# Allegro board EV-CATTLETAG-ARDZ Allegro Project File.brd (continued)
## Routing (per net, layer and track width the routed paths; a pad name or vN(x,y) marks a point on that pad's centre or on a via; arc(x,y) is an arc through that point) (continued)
UNNAMED_4_CN6P_I91_N5: length 5.8
  BOTTOM w0.203: P1.5 3.81,21.59 R75.1
UNNAMED_4_CN6P_I91_N6: length 6.3
  BOTTOM w0.203: R76.1 5.11,20.35 P1.6
UNNAMED_4_CN8PA_I85_N4: length 7.4
  BOTTOM w0.635: R83.1 R82.1 ; R82.1 2.54,45.72 P2.4 ; R82.1 R81.1
UNNAMED_4_CN8PA_I85_N8: length 7.4
  BOTTOM w0.635: R85.1 2.57,35.59 P2.8 ; R85.1 R84.1 ; R85.1 R86.1
UNNAMED_4_CN8PA_I86_N1: length 2.1
  TOP w0.203: P5.1 50.75,17.73 R98.2
UNNAMED_4_CN8PA_I86_N2: length 2.4
  TOP w0.203: P5.2 49.67,20.32 49.63,20.27 49.59,20.27 49.56,20.24 49.21,20.24 48.68,19.71 R97.2
UNNAMED_4_CN8PA_I86_N3: length 2.4
  TOP w0.203: P5.3 50.25,22.3 R96.2
UNNAMED_4_CN8PA_I86_N4: length 2.7
  TOP w0.203: R95.2 49.48,24.08 P5.4
UNNAMED_4_CN8PA_I86_N5: length 3.7
  TOP w0.203: P5.5 49.21,26.34 49.2,26.34 48.68,25.82 R94.2
UNNAMED_4_CN8PA_I86_N6: length 2.1
  TOP w0.203: R93.2 50.8,30.48 P5.6
UNNAMED_4_CN8PA_I86_N7: length 2.1
  TOP w0.203: R92.2 50.75,32.97 P5.7
UNNAMED_4_CN8PA_I86_N8: length 2.1
  TOP w0.203: P5.8 50.75,35.51 R91.2
UNNAMED_4_CN10P_I82_N1: length 2.1
  TOP w0.203: R90.2 50.75,39.57 P4.1
UNNAMED_4_CN10P_I82_N2: length 2.1
  TOP w0.203: P4.2 50.75,42.11 R89.2
UNNAMED_4_CN10P_I82_N3: length 2.2
  TOP w0.203: R100.2 50.8,44.7 P4.3
UNNAMED_4_CN10P_I82_N9: length 2.1
  TOP w0.203: P4.9 50.75,59.89 R88.2
UNNAMED_4_CN10P_I82_N10: length 2.1
  TOP w0.203: R87.2 50.75,62.43 P4.10
UNNAMED_4_DIOLED_I16_N: length 8.5
  TOP w0.508: DS4.C 48.77,71.52 47.62,70.38 46.13,70.38 v1(45.31,69.57) 45.32,69.56 R43.1 45.32,68.5 Q4.1
  BOTTOM w0.203: v1(45.31,69.57) 45.33,69.55 R35.2
UNNAMED_4_DIOLED_I16_P: length 6
  TOP w0.508: DS4.A 50.97,70.8 50.75,70.58 48.89,70.58 47.98,69.67 47.19,69.67 46.91,69.38 R33.2
UNNAMED_4_DIOLED_I122_P: length 2.7
  TOP w0.381: DS2.A 48.46,11.25 v1(47.41,10.21)
  BOTTOM w0.381: R22.2 v1(47.41,10.21)
UNNAMED_4_DIOLED_I130_P: length 4.4
  TOP w0.381: DS3.A 47.29,7.42 v1(46.86,7.42)
  BOTTOM w0.381: R28.2 47.23,7.04 v1(46.86,7.42)
UNNAMED_4_DIOLED_I200_N: length 2.4
  TOP w0.381: R21.1 DS1.C
UNNAMED_4_FERRITE_I266_N2: length 1.4
  BOTTOM w0.381: R53.2 E2.2
UNNAMED_4_FERRITE_I267_N2: length 2
  BOTTOM w0.508: R66.2 25.04,5.94 E4.2
UNNAMED_4_FERRITE_I281_N1: length 2.5
  BOTTOM w0.381: R47.2 R48.2 E1.1
UNNAMED_4_FERRITE_I282_N1: length 2.5
  TOP w0.508: E3.1 19.18,13.29 R62.2 R61.2
UNNAMED_4_RES_I19_N1: length 1.5
  TOP w0.508: R31.2 32.33,66.79 R36.1
UNNAMED_4_RES_I44_N2: length 2.3
  TOP w0.508: R42.2 35.93,69.08 35.92,69.09 RT1.1
UNNAMED_4_RES_I45_N2: length 6.6
  TOP w0.508: R41.2 38.5,65.94 R44.2 40.14,66.61 R44.3
UNNAMED_4_RES_I100_N2: length 2.9
  TOP w0.508: R40.2 44.37,62.89 Q4.3
UNNAMED_4_RES_I121_N1: length 3.5
  BOTTOM w0.381: R20.1 48.84,11.08 Q1.1 ; R20.1 R19.2 ; R20.1 R1.2
UNNAMED_4_RES_I126_N1: length 2.7
  BOTTOM w0.381: Q1.3 48.22,7.36 R22.1
UNNAMED_4_RES_I129_N1: length 2
  BOTTOM w0.508: R28.1 44.98,6.69 Q2.3
UNNAMED_4_RES_I131_N2: length 3.6
  BOTTOM w0.381: R26.2 43.92,10.69 R27.1 ; R27.1 43.91,9.34 Q2.1 ; R27.1 R23.2
UNNAMED_4_RES_I245_N1: length 5
  BOTTOM w0.381: Q5.1 38.87,4.14 R50.2 R51.1 40.44,4.52 R49.2
UNNAMED_4_RES_I261_N2: length 4
  BOTTOM w0.508: Q6.1 20.09,9.1 R63.2 18.36,8.01 R65.1 R64.2
UNNAMED_4_RES_I271_N1: length 7
  BOTTOM w0.381: Q5.2 31.4,2.26 R53.1 31.11,2.56 R54.2
UNNAMED_4_RES_I272_N1: length 3.2
  BOTTOM w0.508: Q6.2 22.46,9.59 R67.2 25.03,9.59 R66.1

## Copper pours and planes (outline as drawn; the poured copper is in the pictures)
GND on TOP (solid shape): 28.47,80.65 28.47,72.44 28.42,72.39 26.76,72.39 26.74,72.42 26.74,73.91 25.16,73.91 25.16,80.47 25.47,80.77 28.34,80.77
GND on TOP (solid shape): 35.4,31.17 35.4,30.2 37.56,28.04 37.56,27.99 36.9,27.99 35.25,29.64 32.76,29.64 32.61,29.79 32.61,31.06 32.76,31.22 35.35,31.22
GND on TOP (solid shape): 43.5,52.88 43.5,51.87 42.61,50.98 37.92,50.98 37.92,52.5 42.49,52.5 43.07,53.09 43.3,53.09
GND on TOP (solid shape): 46.22,31.06 46.22,29.79 46.07,29.64 43.58,29.64 41.93,27.99 41.27,27.99 41.27,28.04 43.43,30.2 43.43,31.17 43.48,31.22 46.07,31.22
GND on TOP (solid shape): 40.79,19.3 41.34,18.75 41.34,15.09 41.06,14.81 40.1,14.81 39.62,15.29 39.62,16.64 37,19.25 36.44,19.25 36.44,20.8 38.65,20.8 39.29,21.44 40.79,21.44
GND on TOP (solid shape): 40.84,40.72 40.84,39.45 40.91,39.37 45.61,39.37 45.76,39.22 45.76,38.25 45.65,38.14 43.34,38.14 43.33,38.13 36.01,38.13 35.88,38.25 35.88,39.22 36.04,39.37 39.13,39.37 39.21,39.45 39.21,40.72 39.39,40.89 40.66,40.89
GND on BOTTOM (solid shape): 36.44,31.47 34.56,31.47 34.41,31.62 34.41,32.84 34.61,33.05 36.44,33.05
GND on BOTTOM (solid shape): 42.49,33.5 42.49,31.55 41.24,31.55 41.24,33.15 41.01,33.38 41.01,34.44 41.14,34.57 41.42,34.57
GND on BOTTOM (solid shape): 45.18,30.84 45.18,29.64 44.93,29.39 42,29.39 41.88,29.51 41.88,29.74 42.56,30.43 43.17,30.43 43.63,30.89 45.13,30.89
GND on TOP: outline of 250 points within 37.51,15.29 52.07,80.77
GND on TOP: 49.27,16.64 51.71,16.64 52.07,16.27 52.07,7.4 51.86,7.19 50.44,7.19 50.13,7.49 50.13,11.91 49.99,12.05 48.57,12.05 48.43,12.19 48.43,14.61 49.27,15.44
GND on TOP: outline of 195 points within 16.33,1.27 52.07,16.64
GND on TOP: 31.36,41.99 33.5,41.99 33.95,41.53 33.95,41 33.73,40.77 33.65,40.73 33.59,40.67 33.57,40.67 33.46,40.64 33.36,40.58 32.46,39.68 32.37,39.61 32.34,39.5 32.34,36.87 32.03,36.56 32.03,32.03 32.09,31.89 32.24,31.83 33.84,31.83 33.98,31.89 34.04,32.03 34.04,32.75 34.08,32.79 34.74,32.79 34.97,32.56 34.97,31.67 34.79,31.5 31.24,31.5 31.08,31.65 31.08,41.71
GND on TOP: 29.31,21.23 29.71,21.23 29.91,21.03 29.91,18.97 29.61,18.67 29.5,18.6 29.45,18.47 29.45,16.82 29.51,16.68 29.65,16.62 31.31,16.62 31.45,16.68 31.51,16.82 31.51,17.47 31.72,17.68 32.36,17.68 32.56,17.68 32.76,17.48 32.76,13.06 32.48,12.78 25.58,12.78 25.11,13.24 25.11,14.12 25.26,14.09 25.4,14.08 26.43,15.11 25.4,16.14 25.26,16.13 25.11,16.1 25.11,16.66 25.26,16.63 25.4,16.62 26.13,16.92 26.43,17.65 26.42,17.75 26.41,17.85 26.41,18.33 26.8,18.72 26.81,18.73
GND on TOP: outline of 237 points within 1.27,1.27 46.88,80.77
GND on BOTTOM: outline of 283 points within 1.27,1.27 48.02,60.12
GND on BOTTOM: 23.72,11.51 30.11,11.51 31.55,10.07 31.69,9.97 31.87,9.93 32.25,9.93 32.53,9.65 32.53,6.86 32.07,6.4 30.85,6.4 30.71,6.34 30.65,6.2 30.65,5.23 30.62,5.2 30.56,5.12 30.54,5.03 30.54,4.1 30.07,3.63 26.43,3.63 26.29,3.57 26.23,3.43 26.23,1.73 25.77,1.27 19.04,1.27 19.04,2.74 19.78,2.74 20.11,3.07 20.11,5.66 20.61,5.66 20.63,5.6 20.67,5.53 20.73,5.47 21.14,5.06 21.31,4.58 21.31,4.57 21.66,3.87 22.4,3.58 22.9,3.7 23.29,4.04 24.07,4.83 26.23,4.83 26.24,4.84 26.33,4.83 27.35,4.83 27.49,4.89 27.55,5.03 27.55,6.81 27.49,6.95 27.35,7.01 26.38,7.01 26.23,7.16 26.23,10.8 23.72,10.8
GND on BOTTOM: 43.78,24.64 39.46,24.64 40.86,23.24 44.34,23.24 44.8,23.7 44.8,24.1 44.7,24.21 44.21,24.21
GND on BOTTOM: outline of 173 points within 1.27,1.27 52.07,80.77
GND on BOTTOM: 45.36,39.37 45.59,39.37 45.74,39.22 45.74,34.14 45.78,33.91 45.91,33.72 46.17,33.46 46.17,29.39 45.97,29.18 45.66,29.18 45.4,29.45 45.4,32.82 45.36,32.94 45.26,33.01 45.23,33.02 44.85,33.4 44.85,33.5 44.82,33.68 44.72,33.83 44.49,34.05 44.49,34.08 44.44,34.22 44.37,34.35 44.37,35.59 45.08,36.3 45.15,36.37 45.18,36.47 45.18,39.19
GND on BOTTOM: outline of 170 points within 6.14,1.27 42.36,18.72
GND on L2_GND, L3_GND: 1.27,80.77 52.07,80.77 52.07,1.27 1.27,1.27
VDD_3V3 on TOP (solid shape): 44.37,50.22 44.37,49.89 44.95,49.3 44.95,49.17 44.93,49.15 43.12,49.15 43.12,49.35 44.01,50.24 44.34,50.24
VDD_3V3 on BOTTOM (solid shape): 24.71,43.2 24.71,40.81 24.61,40.71 24.08,40.71 23.21,41.58 22.68,41.58 22.47,41.78 22.47,42.85 22.68,43.05 23.65,43.05 23.88,43.28 24.63,43.28
B1OUT on TOP (solid shape): 34.31,27.48 34.31,27.15 33.83,26.67 33.83,24.56 33.06,24.56 33.06,26.67 32.68,27.05 32.68,27.41 32.78,27.51 34.28,27.51
B1OUT on TOP (solid shape): 36.09,27.74 38.07,27.74 38.12,27.69 38.12,27.56 37.76,27.2 35.76,27.2 35.4,26.85 32,26.85 31.74,27.1 31.74,28.17 32,28.42 35.4,28.42
B1OUT on BOTTOM (solid shape): 33.19,28.14 33.19,27.13 33.04,26.97 32.28,26.97 31.16,28.09 31.16,28.35 31.18,28.37 32.96,28.37
B2OUT on TOP (solid shape): 46.26,27.48 46.26,27.15 45.78,26.67 45.78,24.56 45.01,24.56 45.01,26.67 44.63,27.05 44.63,27.41 44.74,27.51 46.23,27.51
B2OUT on TOP (solid shape): 47.08,28.17 47.08,27.1 46.83,26.85 43.43,26.85 43.07,27.2 41.06,27.2 40.71,27.56 40.71,27.69 40.76,27.74 42.74,27.74 43.43,28.42 46.83,28.42
B2OUT on BOTTOM (solid shape): 47.14,28.83 47.14,27.53 46.58,26.97 45.76,26.97 45.59,27.15 45.59,28.09 46.45,28.96 47.01,28.96
B2OUT on BOTTOM (solid shape): 28.16,46.15 29.3,46.15 30.55,44.91 30.55,44.65 30.35,44.45 27.07,44.45 26.92,44.6 26.92,46.58 27.73,46.58
BMS_BAT on TOP (solid shape): 43.66,23.47 43.66,22.2 45.13,20.73 45.13,16.43 44.39,15.7 42.36,15.7 42.03,16.03 42.03,18.16 42.04,18.17 42.04,19.1 41.57,19.57 41.57,24.36 39.92,26.01 39.92,27.05 40.07,27.05
BMS_BAT on BOTTOM (solid shape): 45.08,20.93 45.08,20.47 44.47,19.86 44.47,17.3 44.29,17.12 43.27,17.12 41.12,19.28 41.12,20.27 41.29,20.45 41.8,20.45 42.41,21.06 44.95,21.06
BMS_BAT on BOTTOM (solid shape): 18.82,16.46 18.82,12.67 17.68,11.53 15.04,11.53 10.06,6.55 8.61,6.55 8.53,6.63 8.53,7.54 8.59,7.59 8.94,7.59 14.4,13.05 17.02,13.05 17.3,13.33 17.3,16.35 17.5,16.56 18.72,16.56
BMS_SYS on TOP (solid shape): 39.69,26.29 38.97,25.57 38.97,24.19 40.13,23.04 40.13,22.5 38.7,22.5 38.32,22.12 36.54,22.12 36.54,24.97 36.98,25.4 38.12,25.4 39.08,26.37 39.08,26.62 39.21,26.75 39.69,26.75
BMS_SYS on BOTTOM (solid shape): 38.35,24.49 38.35,23.98 38.22,23.85 35.27,23.85 35.15,23.98 35.15,24.13 36.21,25.2 37.64,25.2
L1OUT on TOP (solid shape): 43.4,34.37 43.31,34.19 43.27,33.99 43.28,33.9 43.3,33.81 42.97,33.48 42.26,33.48 41.83,33.91 41.83,37.44 41.85,37.47 43.4,37.47
L1OUT on BOTTOM (solid shape): 42.23,36.04 43.2,36.04 43.4,35.84 43.4,35.26 42.77,34.62 42.26,34.62 41.32,35.56 41.32,36.37 41.34,36.4 41.88,36.4
L1OUT on BOTTOM (solid shape): 29.89,31.57 29.89,30.53 29.66,30.3 28.25,30.3 27.76,29.82 26.95,29.82 26.82,29.95 26.82,31.54 27.05,31.78 29.69,31.78
L2OUT on TOP (solid shape): 40.81,33.91 40.38,33.48 39.67,33.48 39.27,33.88 39.34,34.04 39.36,34.21 39.33,34.41 39.24,34.59 39.24,37.44 39.26,37.47 40.81,37.47
L2OUT on BOTTOM (solid shape): 28.97,27.71 28.97,26.75 28.03,25.8 26.94,25.8 26.74,26.01 26.74,27.83 27.1,28.19 28.49,28.19
L2OUT on BOTTOM (solid shape): 28.19,42.34 29.33,42.34 29.33,41.86 28.92,41.45 28.92,41.07 28.49,40.64 27.02,40.64 27.02,43.03 27.5,43.03
L2OUT on BOTTOM (solid shape): 41.09,36.42 41.06,36.4 41.06,35.53 40.18,34.65 39.85,34.65 39.26,35.23 39.26,35.84 39.41,35.99 40.1,35.99 40.56,36.45 41.06,36.45
L3OUT on TOP (solid shape): 38.22,34.59 38.13,34.41 38.09,34.21 38.12,34.04 38.19,33.88 37.79,33.48 37.08,33.48 36.65,33.91 36.65,37.44 36.67,37.47 38.22,37.47
L3OUT on BOTTOM (solid shape): 38.19,35.84 38.19,35.1 37.74,34.65 36.92,34.65 36.09,35.48 36.09,35.84 36.24,35.99 38.04,35.99
SRC on TOP (solid shape): 42.29,58.52 43.46,58.52 43.66,58.31 43.66,57.2 42.67,56.21 42.67,53.89 42.52,53.75 37.15,53.75 36.26,54.64 36.26,54.81 37.3,54.81 37.84,55.35 40.09,55.35 40.64,55.9 40.64,56.34 40.63,56.34 40.63,58.04 39.93,58.74 39.2,58.74 38.33,59.61 38.33,59.81 38.68,60.17 40.64,60.17
UNNAMED_4_ADMAX20335_I34_B1LX on TOP (solid shape): 37.74,26.44 36.29,26.44 35.4,25.55 35.4,24.28 34.69,24.28 34.69,25.78 35.91,27 38.3,27
UNNAMED_4_ADMAX20335_I34_B2LX on TOP (solid shape): 44.14,25.78 44.14,24.28 43.43,24.28 43.43,25.55 42.54,26.44 41.09,26.44 40.53,27 42.92,27
UNNAMED_4_ADMAX20335_I34_L1OUT on TOP (solid shape): 42.97,32.46 40.4,29.9 40.33,29.9 40.33,30.45 42.26,32.39 42.26,33.07 42.97,33.07
UNNAMED_4_ADMAX20335_I34_L2OUT on TOP (solid shape): 40.38,30.94 40,30.56 39.67,30.89 39.67,33.07 40.38,33.07
UNNAMED_4_ADMAX20335_I34_L3OUT on TOP (solid shape): 37.79,32.36 39.69,30.45 39.69,29.87 39.67,29.84 39.64,29.84 37.08,32.41 37.08,33.07 37.79,33.07
UNNAMED_4_ADMAX20361_I6_LX on TOP (solid shape): 39.57,57.78 39.57,56.26 38.3,56.26 37.16,55.11 36.27,55.11 36.27,55.29 36.53,55.55 36.88,55.55 39.14,57.81 39.55,57.81
UNNAMED_4_CN2P_I136_N2 on BOTTOM (solid shape): 10.66,4.68 10.66,3.43 9.62,2.39 3.7,2.39 3.19,2.9 3.19,3.96 4.16,4.93 10.41,4.93
UNNAMED_4_NCTESTPAD_I165_N1 on BOTTOM (solid shape): 16,20.5 16,13.84 15.79,13.64 13.91,13.64 12.16,15.39 12.16,22.53 13.96,22.53

Small or netless copper shapes (teardrops, artwork), in the pictures only: 66 on BOTTOM, 68 on TOP, 2 on L2_GND, 2 on L3_GND

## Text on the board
Ref Des/Silkscreen Bottom: K | GND | P7 | TMP | SECONDARY SIDE | EV-CATTLETAG-ARDZ | 08-079920 REV B Z | P6 | SRC | LOAD | 5 | 6 | BAT
User.Comments: COMPONENT KEEPOUT AREA | COMPONENTS GREATER THAN 1.5MM | -R77,R79 | -R29 | -R50,R64 | -R51,R65 | -R54,R67 | -C23,C26 | -P3 | -R9,R11,R16,R18,R42,R47,R61,R71,R73,R82,R83,R84,R85,R97 | -R24,R25,R30,R56,R57,R58,R59,R60 | 6.    THE FOLLOWING PARTS ARE DNI(DO NOT INSTALL): | A. P1 | B. P2 | C. P4 | D. P5 | 5.    DO NOT TRIM EXCESS PINS FOR THE FOLLOWING LOCATIONS | WITH LEAD-FREE AND RoHS PCB ASSEMBLY STANDARDS (EU RoHS | DIRECTIVE 2002/95/EC). | 4.    RoHS COMPLIANCE. ASSEMBLY VENDOR SHOULD ASSURE COMPLIANCE
Ref Des/Assembly Top: WIRE ENTRY
Ref Des/Silkscreen Top: 5 | 6 | LOAD | 1 | 2 | 8 | BAT | GND | 10
PAGE_OUTLINE: B | B1 | ECR-116886 | ECR-119049(UPDATE DNI LIST ON ASSY NOTES ONLY) | (NO CHANGE ON LAYOUT AND FAB FILES) | 05DEC23 | 26JAN24 | E. REYTA | EV-CATTLETAG-ARDZ
DIMENSION: -0.60IN | "0" | 2.63IN | DIA MAX | TENTED VIA | SEE FAB NOTES NO. 20 | -0.30IN | 1.80IN
User.10: L2 Internal GND | 08-      -07
User.11: L3 Internal GND | 08-      -08
User.12: FAB NOTES REVISION: 2ND NOVEMBER 2022 | 8.   IMPEDANCE REQUIREMENTS: IF NO STACKUP IS DEFINED, THE VENDOR IS ALLOWED TO ADJUST THE DIELECTRIC | 13.  PLATING SPECIFICATION: | 9.   FILLET OPTIONS TO ENHANCE RELIABILITY AT PAD JUNCTIONS WHERE SPACING PERMITS. | 10.  THIEVING: | 11.  LAYER TO LAYER REGISTRATION SHALL BE WITHIN 0.003 INCHES. | 12.  DRILL SIZES ARE FINISHED HOLE SIZES. ALL HOLES SHALL BE LOCATED WITHIN 0.005 INCHES DTP,UNLESS SPECIFIED. | 14.  SURFACE FINISH: | 15.  SOLDERMASK: | 1.   DIMENSIONS ARE IN INCHES (EXCEPT WHERE NOTED). | ALL DOCUMENTS & SPECIFICATIONS REFERRED TO BELOW SHOULD BE THE LATEST REVISIONS. | 2.  BOARD MATERIAL:(USE CHECKED ITEMS) | 3.   ALL LAMINATES & BONDING MATERIALS SHOULD BE SELECTED FROM IPC-4101 OR IPC-4103,(TG>170 DEGC TD>300 DEGC) | 4.   REFER TO IPC-6010 SERIES, CLASS 2 FOR FABRICATION. | 5.   REFER TO LAMINATION DIAGRAM FOR OVERALL BOARD THICKNESS, TOLERANCE APPLIES AFTER ALL LAMINATION AND PLATING | 6.   BOW & TWIST NOT TO EXCEED 0.0075 INCHES (0.75%) PER LINEAR INCH AND SHOULD BE MEASURED PER IPC-TM-650, METHOD 2.4.22. | 7.   ACCEPTABILITY PER ADI SPECIFICATION TST00115. | 16.  APPLY SILKSCREEN TO BOTH SIDES USING A NON-CONDUCTIVE, EPOXY BASED INK PER ARTWORK. | ( ) FILLETS ALLOWED | ( ) FILLETS NOT ALLOWED | ( ) VENDOR MAY ADD THIEVING TO COMPENSATE FOR LOW COPPER DENSITY AREAS MAINTAINING A MINIMUM | ( ) VENDOR MAY NOT ADD THIEVING TO COMPENSATE FOR LOW COPPER DENSITY AREAS. | (X) LPI | ( ) OTHER_________ | COLOR | ( ) GREEN | (X) OTHER_________ | (X) WHITE | ( ) OTHER | HINDER PROPER SOLDER WICKING. BARREL RELIEF ON SOLDERMASK ALLOWED IN UNFILLED VIA IN PAD HOLES. | (X) REFER TO LAMINATION DIAGRAM FOR FINISHED COPPER WEIGHT/THICKNESS REQUIRMENTS | (X) IMMERSION GOLD (ENIG) 1.58-3.94 MICRO INCHES OVER 118-236 MICRO INCHES MIN. OF ELECTROLESS NICKEL PER IPC-4552 | ( ) OSP (ORGANIC SOLDERABILITY PRESERVATIVE) | ( ) IMMERSION SILVER | ( ) SOFT WIRE BONDABLE GOLD 30-50 MICRO INCHES OF SOFT WIRE | ( ) EDGE CONNECTOR FINGERS ARE TO BE PLATED WITH 100 MICRO-INCHES(.0001") OF LOW STRESS | ( ) OTHER: | THICKNESS & TRACE WIDTHS TO MEET THE IMPEDANCE REQUIREMENT. IF SPECIFIED, THE VENDOR MUST | TRACE WIDTH & SPACING THAT IMPACT THE REQUIREMENTS MUST HAVE WRITTEN APPROVAL FROM ADI. | MINIMUM BARREL PLATING OF 0.001 INCHES. PLATED HOLES SHALL NOT BE ROUGH OR IRREGULAR SO AS TO | SOLDERMASK OVER BARE COPPER OR BARE GOLD (BOTH SIDES) TO MEET IPC-SM-840. | IF PRESENT,DO NOT MODIFY SOLDERMASK DEFINED PADS (MASK OPENINGS LESS THAN COPPER PAD) WITHOUT APPROVAL. | MEET THE REQUIREMENTS LISTED IN THE IMPEDANCE TABLE. ANY ADJUSTMENT MADE TO THE DEFINED STACKUP, | PROCESSES. FINISHED THICKNESS MEASURED FROM TOP COPPER TO BOTTOM COPPER. | (X)  ISOLA 370HR OR EQUIVALENT | ( )  ISOLA-FR408HR OR EQUIVALENT | ( )  ISOLA IS410 | ( )  MEGTRON 6 | ( )  NELCO-4000-13 | ( )  ROGERS 4350B | ( ) ROGERS 3003 | ( ) ARLON 85N | ( ) EM370D | ( )  OTHER ________________________ | X | UL FLAMMABILITY RATING 94V-0. BOARD MATERIAL & CONSTRUCTION SHALL MEET THE REQUIREMENTS OF UL796/UL796F. | BONDABLE GOLD OVER 100-150 MICRO INCHES OF NICKEL | NICKEL UNDER 30 MICRO-INCHES (.0003') OF GOLD | 0.100 INCH CLEARANCE FROM ALL COPPER FEATURES, | THE STARTING COPPER WEIGHT/THICKNESS CAN VARY AS LONG AS THE FINISHED COPPER | WEIGHT/THICKNESS IS NOT LESS THAN THE SPECIFIED VALUE. | UNLESS OTHERWISE SPECIFIED | BLUE | HOMOGENOUS MATERIALS IN THIS BOARD SHALL BE COMPLAINT WITH THE EU DIRECTIVE 2002/95/EC | WORKMANSHIP SHALL CONFORM TO IPC-A-600, CLASS 2. | 21.  INTENTIONAL SHORTS: | 17.  FINAL ELECTRICAL TEST TO BE PERFORMED USING PROVIDED IPC-D-356A NETLIST OR ODB++ FORMAT FILE. | 22.  PEMNUTS: | 23.  MANUFACTURER TO ETCH/STAMP WITH PERMANENT NON-CONDUCTIVE INK | ON SECONDARY SIDE UNLESS OTHERWISE SPECIFIED: | 18.  A TIME DOMAIN REFLECTOMETER REPORT (TDR) FOR EACH IMPEDANCE CONTROLLED LAYER & A CERTIFICATE | 19.  IF PRESENT, ALL BLIND/BURIED VIAS WITH AN ASPECT RATIO <1:1 TO BE PLATED SHUT WITH COPPER WHEN | 20.  FOR VIA FILL INFORMATION REFER TO DRILL CHART: | 24.  MINIMUM DESIGN LINE WIDTH IS .004 INCH. | 25.  MINIMUM DESIGN LINE SPACING IS .004 INCH. | 26.  BOARDS TO BE SHIPPED SINGULATED AFTER FABRICATION PROCESS | SMOOTHEN EDGES AND FREE FROM BURRS AFTER DEPANELIZATION PROCESS | IS ACCEPTABLE, ALL OTHER INSTANCES MUST BE REPORTED. | IF AN INTENTIONAL SHORT REPORT IS SUPPLIED AND DOES NOT MATCH THE FAB DATA THEN | THE PCB SHALL HAVE A VERIFICATION STAMP. | (X)  NON-CONDUCTIVE EPOXY FILL ALL 0.0050 INCHES DRILLED VIAS | ( )  COPPER FILL ALL 0.XXXX INCHES DRILLED VIAS | ( ) PEMNUTS TO BE INSTALLED BY FABRICATOR | ( ) PEMNUTS NOT TO BE INSTALLED BY FABRICATOR | ( ) NOT APPLICABLE | USED AS VIA-IN-PAD OR AS A STACKED VIA. BLIND/BURIED VIAS WITH AN ASPECT RATIO >1:1 TO BE FILLED | A. UL CODE-FLAMMABILITY RATING FOR THOSE APPROVED MATERIALS(IF APPLICABLE) | B. DATE CODE | C. LOT NUMBER | D. MANUFACTURER LOGO | CAN'T BE PERFORMED BECAUSE THE TRACE LENGTH IS TOO SHORT ON THE OUTER LAYERS AT THE PIN ESCAPES | ADI APPROVAL IS REQUIRED. | OF COMPLIANCE SHALL BE PROVIDED BY VENDOR AT TIME OF SHIPMENT. INSTANCES WHERE TDR TESTING | WITH NON-CONDUCTIVE EPOXY. | TOOLING: | FINISH: | NOTES: | MATERIAL: | TESTING: | MISCELLANEOUS:
User.19: L2 GND | 08-      -07
User.20: L3 GND | 08-      -08
User.35: PER ECR-094468 | B | 28MAY20 | PD
User.37: PAGE 1 OF 5 | TOP SIDE VIEW | VIEW OF SILKSCREEN, PINS, VIAS, | ETCH AND REFERENCE INFORMATION. | TEMPLATE NOTES. | 01.COMPONENTS ARE PLACED ON THIS SIDE. | 02.CONNECTORS P1,P2.P4 & P5 ARE PLACED | ON THIS SIDE OF THE BOARD. | 03.IF THE BOARD NEEDS TO BE INCREASED | IT CAN BE INCREASED IN THE DIRECTION | OF THE ARROWS. | 04.THE BOARD IS SET-UP AS A 4 LAYER | BOARD. MAKE SURE ANY SUBSEQUENT CHANGES, | MANUAL OR AUTOMATIC, DO NOT RESULT IN | ANY UNINTENDED CONSEQUENCES. | 05.THE EXISTING ROUTING CAN BE ALTERED AS | IS ROUTED TO CLOSE THE NETS ON THE | TEMPLATE BOARD.
User.38: PAGE 2 OF 5 | BOTTTOM SIDE VIEW | VIEW OF SILKSCREEN, PINS, VIAS, | ETCH AND REFERENCE INFORMATION. | TEMPLATE NOTES. | 01.COMPONENTS ARE PLACED ON THIS SIDE. | 02.CONNECTORS P3 IS PLACED ON THIS SIDE. THE | OTHER CONNECTORS ARE SOLDERED THIS SIDE. | 03.THE TEMPLATE IS VIEWED LOOKING FROM THE | TOP SIDE OF THE BOARD. THE RESULT IS | THAT TEXT IS MIRRORED. | 04.THE BOARD IS SET-UP AS A 4 LAYER | BOARD. MAKE SURE ANY SUBSEQUENT CHANGES, | MANUAL OR AUTOMATIC, DO NOT RESULT IN | ANY UNINTENDED CONSEQUENCES.
User.39: PAGE 3 OF 5 | PCB FAB SHEET 1 | NCDRILL LEGEND, APPROPRIATE | DETAILS AND OUTLINE DIMENSION NOTES. | 01. EACH TIME THE NC DRILL LEGEND | IS RUN, THE HOLE CHART MUST BE | CHECKED TO ASSURE THE TOLERANCES | & NOTES CORRESPOND TO THE RIGHT | PADSTACKS.
User.40: PAGE 4 OF 5 | PCB FAB SHEET 2 | FABRICATION NOTES. ALTER DEPENDING ON THE | REQUIREMENTS OF THE DESIGN.
User.41: TEMPLATE REVISION HISTORY | TEMPLATE BOARDS FOR EVAL PROVIDE INFORMATION IN THE | 5-VIEW "PDF FORMAT" FOR EVAL ENGINEERING | REFERENCE; ALONG WITH EMBEDDED ALLEGRO | PROPERTIES FOR PCB DESIGN USE. | THEY MAINTAIN A SEPARATE TITLE BLOCK AND PART | NUMBER FOR REVISION TRACKING, INDEPENDENT OF | THE ACTUAL MANUFACTURED DUT-SPECIFIC BOARD | DESIGN. | TEMPLATE BOARDS DISPLAY AS "FILE VIEWS", AND | DUT-SPECIFIC APPLICATION BOARDS ARE | MANUFACTURED FROM ARTWORK "FILM VIEWS"AND NC | DATA. | AND TITLE BLOCK CONTENT IS TRACKING THE | MANUFACTURED BOARD PART NUMBER AND REV, | AND NOT THE TEMPLATE BOARD PART NUMBER AND | REV. | PAGE 5 OF 5 | MAKE SURE THE DUT-SPECIFIC BOARD INFORMATION | REV.A (20APR20) | 1. INITIAL RELEASE. | REV.B (28MAY20) PER ECR-094468 | 1. BRING FILES INTO TEMPLATE FORMAT.
User.45: 1 | FABRICATION | 09-012345-01 | A | FIGURE | SIZE | 5.0 | 10.0 | 15.0 | 35.0 | 45.0 | 50.0 | 55.0 | 93.0 | 125.0 | PLATED | NON-PLATED | FINISHED HOLES IN MILS | ALL UNITS ARE IN MILS | QTY | 16 | 283 | 21 | 2 | 38 | 8 | 4 | TOLERANCE/NOTES
